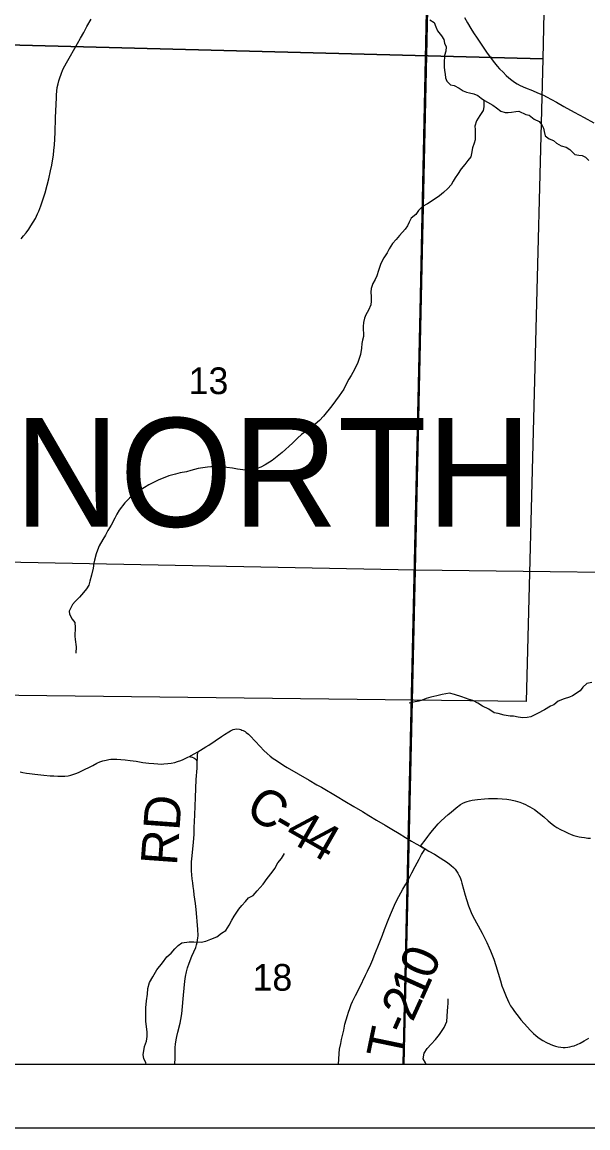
# Model space of a CAD drawing. Extents: x -19.9 to 41.9, y 0 to 32.3.
# Drawn here: x 7.228 to 8.114, y 14 to 15.733 of the extents above; entities that cross this region are included whole.
import ezdxf

# ---------------------------------------------------------------- set-up
doc = ezdxf.new("R2010")
doc.units = 0
for name, color, linetype in [('GM_X_Corporation', 7, 'Continuous'), ('GM_X_County_Road', 7, 'Continuous'), ('GM_X_County_Road_Text', 7, 'Continuous'), ('GM_X_Minor_River', 7, 'Continuous'), ('GM_X_Section', 7, 'Continuous'), ('GM_X_Section_Text', 7, 'Continuous'), ('GM_X_Township_Road', 7, 'Continuous'), ('GM_X_Township_Road_Text', 7, 'Continuous'), ('GM_X_Township_Text', 7, 'Continuous'), ('SH_Data', 7, 'Continuous')]:
    doc.layers.add(name, color=color, linetype=linetype)

msp = doc.modelspace()

# ---------------------------------------------------------------- linework, layer by layer
at = {"layer": 'GM_X_Corporation'}
for points in [[(2.1, 17.918), (2.1, 14.1), (8.9, 14.1), (8.9, 17.8974), (7.9072, 17.9171), (7.5529, 17.9242), (7.3858, 17.9277), (6.9468, 17.937), (6.7, 17.9422), (6.3069, 17.9505), (6.2497, 17.9517), (6.2397, 17.9517), (5.9048, 17.9534), (5.761, 17.9543), (5.4954, 17.9559), (5.0257, 17.9637), (5.0192, 17.8403), (4.9169, 17.8392), (4.2613, 17.8672), (3.984, 17.879), (3.7505, 17.884), (2.973, 17.9007), (2.4715, 17.9106)], [(7.8246, 14.1), (8.9, 14.1), (8.9, 17.8974), (7.9072, 17.9171), (7.9012, 17.4524), (7.8776, 16.5173), (7.8702, 16.1679), (7.854, 15.4058), (7.8518, 15.3043)], [(7.8659, 15.8953), (7.8436, 14.8739), (6.8226, 14.894), (6.8522, 15.9041)], [(8.8854, 15.8688), (8.8595, 14.8618), (7.8436, 14.8739), (7.8659, 15.8953)], [(6.8053, 14.1), (7.8255, 14.1), (7.8436, 14.8739), (6.8226, 14.894)], [(7.8255, 14.1), (8.8418, 14.1), (8.8595, 14.8618), (7.8436, 14.8739)]]:
    msp.add_lwpolyline(points, close=True, dxfattribs=at)
msp.add_lwpolyline([(2.1, 17.918), (2.1, 14.1), (7.8246, 14.1), (7.8518, 15.3043), (7.854, 15.4058), (7.8702, 16.1679), (7.8776, 16.5173), (7.9012, 17.4524), (7.9072, 17.9171)], dxfattribs=at)
at = {"layer": 'GM_X_County_Road'}
for points in [[(7.2262, 15.3936), (7.2302, 15.3981), (7.2343, 15.403), (7.2384, 15.4088), (7.2418, 15.4138), (7.2452, 15.4195), (7.2486, 15.4254), (7.252, 15.4324), (7.254, 15.4368), (7.2572, 15.445), (7.2605, 15.4546), (7.2638, 15.4653), (7.2671, 15.4774), (7.2697, 15.4877), (7.2726, 15.5), (7.2745, 15.509), (7.2762, 15.519), (7.2768, 15.5247), (7.2777, 15.5326), (7.2785, 15.5404), (7.2795, 15.5598), (7.2804, 15.5831), (7.2815, 15.6147), (7.2818, 15.6189), (7.2822, 15.625), (7.2829, 15.6308), (7.2841, 15.6361), (7.2853, 15.6412), (7.2868, 15.6459), (7.2889, 15.6517), (7.2918, 15.6586), (7.2949, 15.6644), (7.2974, 15.669), (7.3148, 15.6997), (7.3193, 15.7077), (7.3246, 15.7168), (7.3295, 15.7261), (7.3361, 15.7377)], [(7.9207, 15.7403), (7.9256, 15.7321), (7.9304, 15.7233), (7.9348, 15.7165), (7.9405, 15.7079), (7.9552, 15.6861), (7.9626, 15.6759), (7.9677, 15.6692), (7.9719, 15.6639), (7.9753, 15.6601), (7.9811, 15.6544), (7.9859, 15.6495), (7.9904, 15.6456), (7.9947, 15.6422), (7.9991, 15.6391), (8.0032, 15.6365), (8.008, 15.6339), (8.0162, 15.6302), (8.0274, 15.6257), (8.0353, 15.6224), (8.0447, 15.6184), (8.0493, 15.6161), (8.0648, 15.6075), (8.0764, 15.601), (8.0927, 15.592), (8.108, 15.5835), (8.1232, 15.5751)], [(7.2248, 14.5581), (7.2288, 14.557), (7.2348, 14.5559), (7.2396, 14.5552), (7.2477, 14.5544), (7.2618, 14.5529), (7.2716, 14.552), (7.2778, 14.5516), (7.2839, 14.5512), (7.2889, 14.5511), (7.2946, 14.5514), (7.2998, 14.552), (7.3042, 14.5528), (7.3089, 14.5542), (7.3134, 14.5557), (7.317, 14.5573), (7.3206, 14.559), (7.3385, 14.5682), (7.3451, 14.5714), (7.3496, 14.5735), (7.3545, 14.5751), (7.3596, 14.5764), (7.3635, 14.5772), (7.367, 14.5778), (7.3711, 14.578), (7.3761, 14.5778), (7.3825, 14.5774), (7.3895, 14.5767), (7.3973, 14.5759), (7.4067, 14.5746), (7.417, 14.5729), (7.4263, 14.5717), (7.4343, 14.5709), (7.4403, 14.5705), (7.4457, 14.5702), (7.4498, 14.5704), (7.4563, 14.5709), (7.4612, 14.5716), (7.4669, 14.5728), (7.4712, 14.574), (7.4767, 14.5758), (7.4803, 14.5773), (7.4874, 14.5808), (7.4898, 14.5821), (7.4928, 14.5837), (7.4974, 14.5863), (7.5031, 14.5896), (7.5154, 14.5971), (7.5202, 14.5999), (7.54, 14.6133), (7.5447, 14.6165), (7.5514, 14.6206), (7.5542, 14.6223), (7.5584, 14.6242), (7.5611, 14.6249), (7.5642, 14.6253), (7.5682, 14.6249), (7.5702, 14.6244), (7.5722, 14.6236), (7.574, 14.6228), (7.5771, 14.6212), (7.579, 14.6197), (7.5822, 14.6169), (7.5848, 14.6144), (7.6007, 14.5975), (7.6067, 14.5914), (7.6118, 14.5868), (7.6165, 14.5827), (7.6213, 14.5791), (7.6262, 14.5756), (7.6378, 14.568), (7.643, 14.5648), (7.6775, 14.545), (7.6896, 14.5379), (7.6969, 14.5338), (7.7212, 14.5196), (7.7335, 14.5121), (7.7474, 14.5038), (7.761, 14.4958), (7.771, 14.4898), (7.7828, 14.4825), (7.7966, 14.4743), (7.8069, 14.4681), (7.8185, 14.4612), (7.8283, 14.4553), (7.8379, 14.4496), (7.8453, 14.4453), (7.852, 14.4413)], [(7.852, 14.4413), (7.8558, 14.4391), (7.859, 14.4372)], [(7.859, 14.4372), (7.8651, 14.4337), (7.8735, 14.4289), (7.8825, 14.4235), (7.8884, 14.4198), (7.8928, 14.4168), (7.8966, 14.414), (7.9, 14.4114), (7.9034, 14.4082), (7.9061, 14.4053), (7.9081, 14.4026), (7.9102, 14.3992), (7.9121, 14.3962), (7.9139, 14.3923), (7.9155, 14.3875), (7.9168, 14.3836), (7.9218, 14.3647), (7.9238, 14.3578), (7.9271, 14.3479), (7.9289, 14.343), (7.9312, 14.3377), (7.9335, 14.333), (7.9482, 14.305), (7.9514, 14.2991), (7.9556, 14.2908), (7.9592, 14.2824), (7.9613, 14.2775), (7.9666, 14.2642), (7.9696, 14.2547), (7.9769, 14.2306), (7.9793, 14.2228), (7.9816, 14.2165), (7.9861, 14.2057), (7.9881, 14.201), (7.9903, 14.1964), (7.993, 14.1914), (7.9958, 14.1869), (7.9989, 14.1823), (8.0061, 14.1728), (8.0088, 14.1694), (8.0192, 14.158), (8.0238, 14.1531), (8.0289, 14.1481), (8.0325, 14.1448), (8.0357, 14.1423), (8.041, 14.1387), (8.0435, 14.1371), (8.0494, 14.1338), (8.0547, 14.1312), (8.0588, 14.1296), (8.0635, 14.1281), (8.0675, 14.127), (8.0715, 14.1263), (8.0751, 14.1261), (8.0786, 14.1259), (8.0824, 14.1263), (8.0855, 14.1269), (8.0895, 14.1279), (8.0924, 14.1288), (8.0971, 14.1308), (8.1021, 14.133), (8.1079, 14.1363), (8.1155, 14.1405)]]:
    msp.add_lwpolyline(points, dxfattribs=at)
at = {"layer": 'GM_X_Minor_River'}
for points in [[(7.8667, 15.7365), (7.8732, 15.7325), (7.8756, 15.7256), (7.8783, 15.7196), (7.8845, 15.7117), (7.8884, 15.7057), (7.8892, 15.7003), (7.892, 15.6943), (7.8913, 15.6874), (7.8895, 15.6806), (7.8889, 15.6695), (7.889, 15.663), (7.8895, 15.6573), (7.8903, 15.6516), (7.8911, 15.6456), (7.8931, 15.6403), (7.8989, 15.635), (7.9046, 15.6336), (7.9122, 15.6295), (7.9187, 15.6254), (7.9237, 15.6232), (7.9286, 15.6222), (7.9351, 15.6204), (7.9415, 15.6182), (7.9469, 15.6141), (7.9519, 15.6103), (7.9568, 15.6078), (7.9652, 15.6029), (7.971, 15.5988), (7.9775, 15.5936), (7.9843, 15.5914), (7.9892, 15.5915)], [(7.9508, 15.6111), (7.9509, 15.6004), (7.9502, 15.5947), (7.945, 15.5866), (7.9395, 15.5786), (7.9369, 15.5698), (7.9374, 15.5648), (7.9375, 15.5538), (7.9372, 15.5485), (7.9358, 15.5431), (7.9333, 15.5358), (7.9315, 15.5271), (7.9304, 15.5221), (7.926, 15.5163), (7.9211, 15.5101), (7.9156, 15.5032), (7.9096, 15.4944), (7.9059, 15.489), (7.903, 15.4836), (7.8997, 15.4778), (7.8944, 15.4721), (7.8881, 15.4659), (7.8817, 15.4608), (7.8716, 15.4538), (7.863, 15.4484), (7.8547, 15.444), (7.8487, 15.4379), (7.8447, 15.4317), (7.8372, 15.4259), (7.8339, 15.4194), (7.8317, 15.4136), (7.8276, 15.4086), (7.819, 15.3986), (7.8138, 15.3924), (7.8082, 15.3859), (7.8027, 15.3778), (7.7994, 15.3716), (7.7945, 15.3636), (7.7898, 15.3547), (7.7858, 15.3436), (7.7836, 15.3356), (7.7807, 15.3295), (7.777, 15.3233), (7.7744, 15.3157), (7.7738, 15.3096), (7.7746, 15.3028), (7.7747, 15.2959), (7.774, 15.2902), (7.7704, 15.2818), (7.7663, 15.2741), (7.7641, 15.2691), (7.7623, 15.2622), (7.762, 15.2561), (7.7621, 15.2508), (7.7626, 15.2455), (7.7623, 15.2405), (7.7612, 15.2344), (7.7602, 15.2291), (7.7595, 15.2222), (7.7581, 15.2119), (7.753, 15.1978), (7.7457, 15.1839), (7.7431, 15.179), (7.7398, 15.1732), (7.7357, 15.1667), (7.7317, 15.1578), (7.7243, 15.1471), (7.7131, 15.1317), (7.6997, 15.1155), (7.6938, 15.1089), (7.687, 15.1027), (7.6814, 15.0981), (7.6736, 15.0926), (7.6657, 15.0868), (7.6593, 15.081), (7.6515, 15.0733), (7.6351, 15.0585), (7.6197, 15.0458), (7.6088, 15.0391), (7.6017, 15.0356), (7.5904, 15.0316), (7.5843, 15.0311), (7.5775, 15.0306), (7.565, 15.0324), (7.5574, 15.0338), (7.5487, 15.0348), (7.5388, 15.0361), (7.5335, 15.0364), (7.5237, 15.0363), (7.518, 15.0354), (7.5037, 15.0337), (7.492, 15.0305), (7.4856, 15.0281), (7.4754, 15.0264), (7.4682, 15.0244), (7.4576, 15.022), (7.4411, 15.0152), (7.4264, 15.0078), (7.4129, 14.9996), (7.4017, 14.9914), (7.3961, 14.9868)], [(7.9892, 15.5915), (7.9945, 15.592), (8.001, 15.5928), (8.0059, 15.5933), (8.0169, 15.5881), (8.0222, 15.5871), (8.0299, 15.5807), (8.0379, 15.5774), (8.0418, 15.5721), (8.0445, 15.5668), (8.0453, 15.5615), (8.0473, 15.5547), (8.0531, 15.5502), (8.0599, 15.5477), (8.0649, 15.5432), (8.0722, 15.5391), (8.0798, 15.5369), (8.0855, 15.5332), (8.0936, 15.5257), (8.0996, 15.5243), (8.105, 15.524), (8.1103, 15.5214), (8.1153, 15.5162)], [(7.3961, 14.9868), (7.389, 14.9798), (7.3797, 14.9679), (7.376, 14.9617), (7.373, 14.9556), (7.3671, 14.9448), (7.3623, 14.9364), (7.3583, 14.9291), (7.3542, 14.9222), (7.3487, 14.9122), (7.3457, 14.9057), (7.3439, 14.8996), (7.3414, 14.89), (7.34, 14.885), (7.339, 14.8774), (7.3365, 14.8663), (7.334, 14.8568), (7.3322, 14.8507), (7.3288, 14.8449), (7.324, 14.8391), (7.318, 14.8318), (7.3109, 14.8252), (7.3069, 14.8202), (7.3017, 14.8099), (7.3022, 14.8049), (7.3064, 14.7974), (7.3103, 14.7921), (7.3108, 14.7845), (7.3106, 14.7708), (7.3111, 14.7655), (7.3124, 14.7541), (7.312, 14.7442)], [(8.12, 14.6983), (8.1121, 14.6963), (8.1061, 14.6909), (8.1017, 14.6851), (8.09, 14.6773), (8.0851, 14.6753), (8.0769, 14.6722), (8.0675, 14.6686), (8.0607, 14.6632), (8.0554, 14.6608), (8.0461, 14.6553), (8.0352, 14.6494), (8.0246, 14.6443), (8.019, 14.6431), (8.0122, 14.6426), (8.0046, 14.6436), (7.9974, 14.6451), (7.9921, 14.6454), (7.983, 14.6467), (7.9735, 14.6493), (7.967, 14.6507), (7.959, 14.6563), (7.9487, 14.6611), (7.9418, 14.6655), (7.9338, 14.6696), (7.9281, 14.6714), (7.9167, 14.6758), (7.9049, 14.6794), (7.8973, 14.6812), (7.8916, 14.6804), (7.8859, 14.6791), (7.8776, 14.6771), (7.8682, 14.675), (7.8607, 14.673), (7.8543, 14.6703), (7.849, 14.6687), (7.8407, 14.667), (7.8343, 14.6658)], [(7.4223, 14.1), (7.4215, 14.1022), (7.4183, 14.1087), (7.4175, 14.1147), (7.4196, 14.1273), (7.4225, 14.1358), (7.4239, 14.143), (7.4238, 14.1506), (7.4229, 14.1586), (7.4216, 14.1673), (7.4215, 14.1795), (7.4217, 14.1883), (7.4227, 14.1989), (7.4241, 14.2096), (7.4247, 14.2184), (7.4276, 14.2279), (7.4324, 14.2368), (7.439, 14.2475), (7.4479, 14.2587), (7.4546, 14.2679), (7.4614, 14.2737), (7.4669, 14.2807), (7.4725, 14.2857), (7.4782, 14.29), (7.4895, 14.2917), (7.4967, 14.2914), (7.5081, 14.2912), (7.5156, 14.2928), (7.5235, 14.296), (7.5329, 14.2996), (7.5404, 14.3054), (7.5468, 14.3093), (7.552, 14.3178), (7.5564, 14.3254), (7.5601, 14.3316), (7.5675, 14.3427), (7.572, 14.3485), (7.5775, 14.3547), (7.5824, 14.3605), (7.5899, 14.3644), (7.5959, 14.3713), (7.6055, 14.3821), (7.6115, 14.3906), (7.6193, 14.4006), (7.6237, 14.4064), (7.6282, 14.4156), (7.6341, 14.4222), (7.6389, 14.4298)], [(7.8607, 14.1), (7.8595, 14.1017), (7.856, 14.1081), (7.8574, 14.1173), (7.8622, 14.1246), (7.8686, 14.1312), (7.8753, 14.1385), (7.8816, 14.1466), (7.889, 14.1574), (7.893, 14.1666), (7.8937, 14.1746), (7.8943, 14.1837), (7.8946, 14.1894), (7.8949, 14.1955), (7.8952, 14.2024)]]:
    msp.add_lwpolyline(points, dxfattribs=at)
at = {"layer": 'GM_X_Section'}
for points in [[(8.0651, 16.6907), (8.0435, 15.6754), (7.0239, 15.7019), (7.0463, 16.7153)], [(8.0435, 15.6754), (8.0175, 14.6683), (7.0016, 14.6805), (7.0239, 15.7019)]]:
    msp.add_lwpolyline(points, close=True, dxfattribs=at)
at = {"layer": 'GM_X_Township_Road'}
for points in [[(7.4672, 14.1), (7.4674, 14.1099), (7.4677, 14.1209), (7.4678, 14.1261), (7.4683, 14.1314), (7.4692, 14.138), (7.4704, 14.1432), (7.472, 14.15), (7.4753, 14.1641), (7.4763, 14.1699), (7.4779, 14.1788), (7.4785, 14.1847), (7.4806, 14.2079), (7.4828, 14.2298), (7.484, 14.2373), (7.4856, 14.2448), (7.487, 14.2506), (7.4897, 14.2584), (7.4937, 14.2689), (7.4997, 14.2829), (7.501, 14.2869), (7.5021, 14.2906), (7.5027, 14.2941), (7.5031, 14.2977), (7.5034, 14.3012), (7.5032, 14.3114), (7.5028, 14.3172), (7.5022, 14.3241), (7.5016, 14.3304), (7.5003, 14.3425), (7.4992, 14.3519), (7.4983, 14.3586), (7.4975, 14.3651), (7.4967, 14.372), (7.4959, 14.3784), (7.4951, 14.3843), (7.4944, 14.3905), (7.4938, 14.3968), (7.4933, 14.4027), (7.493, 14.4101), (7.4932, 14.4169), (7.4941, 14.4266), (7.4952, 14.4371), (7.4962, 14.4475), (7.4972, 14.4604), (7.4975, 14.4709), (7.498, 14.4803), (7.4985, 14.4906), (7.4995, 14.5177), (7.5007, 14.5461), (7.5019, 14.5637), (7.5022, 14.5713), (7.5023, 14.5746), (7.5025, 14.5788), (7.5028, 14.5834), (7.5031, 14.5896)], [(7.4898, 14.5821), (7.4916, 14.5816), (7.4942, 14.5809), (7.4966, 14.58), (7.4984, 14.5789), (7.5001, 14.5774), (7.5023, 14.5746)], [(7.852, 14.4413), (7.8605, 14.4528), (7.8634, 14.4566), (7.8666, 14.4609), (7.8707, 14.466), (7.8738, 14.4699), (7.8795, 14.4764), (7.8837, 14.4807), (7.8899, 14.4866), (7.8953, 14.4913), (7.8997, 14.4949), (7.9079, 14.5016), (7.9146, 14.5068), (7.9183, 14.5088), (7.9217, 14.5104), (7.9249, 14.5116), (7.9288, 14.5128), (7.933, 14.5138), (7.9371, 14.5144), (7.9412, 14.5149), (7.9522, 14.5158), (7.9585, 14.516), (7.9652, 14.5162), (7.9722, 14.516), (7.9797, 14.5156), (7.9869, 14.515), (7.9934, 14.514), (8.0002, 14.5125), (8.0074, 14.5104), (8.0126, 14.5083), (8.0165, 14.5067), (8.0199, 14.5049), (8.0229, 14.5034), (8.0266, 14.5013), (8.0304, 14.4988), (8.0376, 14.4935), (8.0452, 14.4875), (8.0517, 14.4815), (8.058, 14.4761), (8.062, 14.4731), (8.0656, 14.4709), (8.0713, 14.4679), (8.078, 14.4644), (8.083, 14.4621), (8.0879, 14.46), (8.092, 14.4585), (8.096, 14.4573), (8.1001, 14.4564), (8.1039, 14.4557), (8.1086, 14.4549), (8.1138, 14.4541), (8.1179, 14.4539)], [(7.7235, 14.1), (7.7239, 14.1077), (7.7243, 14.1164), (7.7251, 14.1232), (7.7268, 14.1321), (7.7283, 14.1386), (7.7315, 14.1534), (7.7334, 14.1623), (7.7373, 14.1762), (7.7389, 14.1813), (7.7409, 14.1871), (7.7433, 14.1934), (7.7453, 14.1982), (7.7499, 14.2075), (7.7567, 14.2207), (7.7659, 14.2393), (7.7689, 14.2456), (7.774, 14.2566), (7.7774, 14.2639), (7.7795, 14.2695), (7.788, 14.2915), (7.7922, 14.3022), (7.7956, 14.3108), (7.8013, 14.3253), (7.805, 14.3343), (7.8111, 14.3489), (7.8143, 14.3558), (7.8179, 14.3628), (7.8242, 14.3741), (7.8286, 14.3819), (7.8333, 14.3905), (7.8381, 14.3996), (7.8437, 14.4097), (7.8496, 14.4212), (7.8536, 14.4287), (7.8556, 14.4318), (7.859, 14.4372)], [(7.859, 14.4372), (7.8558, 14.4391), (7.852, 14.4413)]]:
    msp.add_lwpolyline(points, dxfattribs=at)
at = {"layer": 'SH_Data'}
for p, q in [((2.1, 14.1), (8.9, 14.1)), ((2, 14), (9, 14))]:
    msp.add_line(p, q, dxfattribs=at)

# ---------------------------------------------------------------- texts
at = {"layer": 'GM_X_County_Road_Text'}
for s, rotation, p in [('C', 327.8039, (7.5748, 14.492)), ('4', 330.1168, (7.6366, 14.4541)), ('-', 329.9361, (7.6162, 14.4659)), ('4', 330.2074, (7.667, 14.4366))]:
    msp.add_text(s, height=0.0568, rotation=rotation, dxfattribs=at).set_placement(p)
at = {"layer": 'GM_X_Section_Text'}
for s, p in [('13', (7.4887, 15.15)), ('18', (7.5887, 14.215))]:
    msp.add_text(s, height=0.04186, rotation=0, dxfattribs=at).set_placement(p)
at = {"layer": 'GM_X_Township_Road_Text'}
for s, height, rotation, p in [('RD', 0.05682, 85.814, (7.4702, 14.4102)), ('0', 0.0568, 67.5626, (7.8694, 14.2306)), ('1', 0.0568, 65.7938, (7.8543, 14.1969)), ('2', 0.0568, 65.4135, (7.8395, 14.1647)), ('T', 0.0568, 78.274, (7.8225, 14.105)), ('-', 0.0568, 65.9701, (7.8301, 14.1436))]:
    msp.add_text(s, height=height, rotation=rotation, dxfattribs=at).set_placement(p)
at = {"layer": 'GM_X_Township_Text'}
msp.add_text('NORTH', height=0.17045, rotation=0, dxfattribs=at).set_placement((7.2159, 14.9422))

doc.saveas('drawing.dxf')
